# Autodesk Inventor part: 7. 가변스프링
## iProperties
Created: 2015-01
Part Number: 7. 가변스프링
Document SubType Name: Modeling
Designer: elite
Density: 7.87 g/cm^3
Material: 탄소강
Mass: 79.8619 g
Surface Area: 103.229 cm^2
Volume: 10.1476 cm^3
Author: elite
